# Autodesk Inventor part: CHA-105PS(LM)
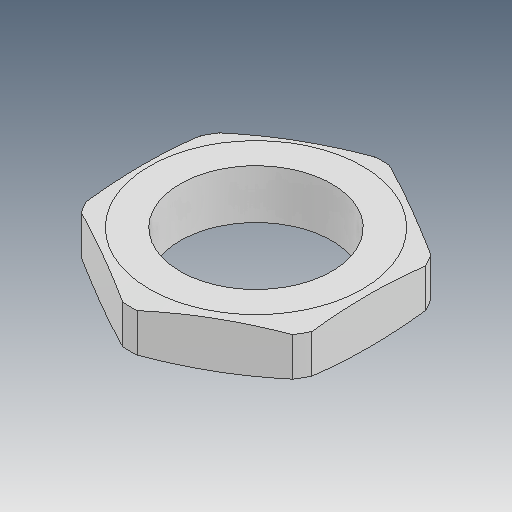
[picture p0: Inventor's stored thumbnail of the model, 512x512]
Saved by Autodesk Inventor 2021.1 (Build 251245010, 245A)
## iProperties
Created: 2021-05
Part Number: CHA-105PS(LM)
Material: Ogólny
Document SubType Name: Modeling
Designer: user
Density: 1 g/cm^3
Appearance: Domyślna
Author: user
Revision Number: ÈÎºÎ
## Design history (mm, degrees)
feature "M39 ÂÝÎÆ¿×1"
node "Bryła1"
